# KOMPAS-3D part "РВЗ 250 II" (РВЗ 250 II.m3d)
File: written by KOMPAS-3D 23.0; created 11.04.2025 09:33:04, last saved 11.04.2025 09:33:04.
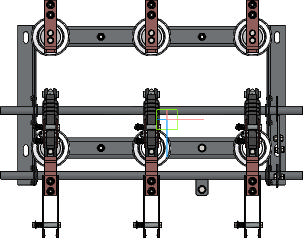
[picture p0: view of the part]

Document properties: Автор: pc; Полное имя файла: C:\Users\pc\Desktop\работа\РВЗ\3D макеты\РВЗ 250 II.m3d

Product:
- Body: Тело 1
    Масса: 0.01131
- Body: Тело 2
    Масса: 0.01131
- Body: Тело 3
    Масса: 0.01131
- Body: Тело 4
    Масса: 0.01131
- Body: Тело 5
    Масса: 1.849184
- Body: Тело 6
    Масса: 0.011176
- Body: Тело 7
    Масса: 0.011176
- Body: Тело 8
    Масса: 0.011176
- Body: Тело 9
    Масса: 0.052628
- Body: Тело 10
    Масса: 1.849184
- Body: Тело 11
    Масса: 0.010034
- Part/product: РВЗ 250 II
    Масса: 3.839795

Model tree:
1. Операция без истории:1
2. Операция без истории:2
3. Операция без истории:3
4. Операция без истории:4
5. Операция без истории:5
6. Операция без истории:6
7. Операция без истории:7
8. Операция без истории:8
9. Операция без истории:9
10. Операция без истории:10
11. Операция без истории:11
12. Поверхность без истории:1
13. Поверхность без истории:2
14. Поверхность без истории:3
15. Поверхность без истории:4
16. Поверхность без истории:5
17. Поверхность без истории:6
18. Поверхность без истории:7
19. Поверхность без истории:8
20. Поверхность без истории:9
21. Поверхность без истории:10
22. Поверхность без истории:11
23. Поверхность без истории:12
24. Поверхность без истории:13
25. Поверхность без истории:14
26. Поверхность без истории:15
27. Поверхность без истории:16
28. Поверхность без истории:17
29. Поверхность без истории:18
30. Поверхность без истории:19
31. Поверхность без истории:20
32. Поверхность без истории:21
33. Поверхность без истории:22
34. Поверхность без истории:23
35. Поверхность без истории:24
36. Поверхность без истории:25
37. Поверхность без истории:26
38. Поверхность без истории:27
39. Поверхность без истории:28
40. Поверхность без истории:29
41. Поверхность без истории:30
42. Поверхность без истории:31
43. Поверхность без истории:32
44. Поверхность без истории:33
45. Поверхность без истории:34
46. Поверхность без истории:35
47. Поверхность без истории:36
48. Поверхность без истории:37
49. Поверхность без истории:38
50. Поверхность без истории:39
51. Поверхность без истории:40
52. Поверхность без истории:41
53. Поверхность без истории:42
54. Поверхность без истории:43
55. Поверхность без истории:44
56. Поверхность без истории:45
57. Поверхность без истории:46
58. Поверхность без истории:47
59. Поверхность без истории:48
60. Поверхность без истории:49
61. Поверхность без истории:50
62. Поверхность без истории:51
63. Поверхность без истории:52
64. Поверхность без истории:53
65. Поверхность без истории:54
66. Поверхность без истории:55
67. Поверхность без истории:56
68. Поверхность без истории:57
69. Поверхность без истории:58
70. Поверхность без истории:59
71. Поверхность без истории:60
72. Поверхность без истории:61
73. Поверхность без истории:62
74. Поверхность без истории:63
75. Поверхность без истории:64
76. Поверхность без истории:65
77. Поверхность без истории:66
78. Поверхность без истории:67
79. Поверхность без истории:68
80. Поверхность без истории:69
81. Поверхность без истории:70
82. Поверхность без истории:71
83. Поверхность без истории:72
84. Поверхность без истории:73
85. Поверхность без истории:74
86. Поверхность без истории:75
87. Поверхность без истории:76
88. Поверхность без истории:77
89. Поверхность без истории:78
90. Поверхность без истории:79
91. Поверхность без истории:80
92. Поверхность без истории:81
93. Поверхность без истории:82
94. Поверхность без истории:83
95. Поверхность без истории:84
96. Поверхность без истории:85
97. Поверхность без истории:86
98. Поверхность без истории:87
99. Поверхность без истории:88
100. Поверхность без истории:89
101. Поверхность без истории:90
102. Поверхность без истории:91
103. Поверхность без истории:92
104. Поверхность без истории:93
105. Поверхность без истории:94
106. Поверхность без истории:95
107. Поверхность без истории:96
108. Поверхность без истории:97
109. Поверхность без истории:98
110. Поверхность без истории:99
111. Поверхность без истории:100
112. Поверхность без истории:101
113. Поверхность без истории:102
114. Поверхность без истории:103
115. Поверхность без истории:104
116. Поверхность без истории:105
117. Поверхность без истории:106
118. Поверхность без истории:107
119. Поверхность без истории:108
120. Поверхность без истории:109
121. Поверхность без истории:110
122. Поверхность без истории:111
123. Поверхность без истории:112
124. Поверхность без истории:113
125. Поверхность без истории:114
126. Поверхность без истории:115
127. Поверхность без истории:116
128. Поверхность без истории:117
129. Поверхность без истории:118
130. Поверхность без истории:119
131. Поверхность без истории:120
132. Поверхность без истории:121
133. Поверхность без истории:122
134. Поверхность без истории:123
135. Поверхность без истории:124
136. Поверхность без истории:125
137. Поверхность без истории:126
138. Поверхность без истории:127
139. Поверхность без истории:128
140. Поверхность без истории:129
141. Поверхность без истории:130
142. Поверхность без истории:131
143. Поверхность без истории:132
144. Поверхность без истории:133
145. Поверхность без истории:134
146. Поверхность без истории:135
147. Поверхность без истории:136
148. Поверхность без истории:137
149. Поверхность без истории:138
150. Поверхность без истории:139
151. Поверхность без истории:140
152. Поверхность без истории:141
153. Поверхность без истории:142
154. Поверхность без истории:143
155. Поверхность без истории:144
156. Поверхность без истории:145
157. Поверхность без истории:146
158. Поверхность без истории:147
159. Поверхность без истории:148
160. Поверхность без истории:149
161. Поверхность без истории:150
162. Поверхность без истории:151
163. Поверхность без истории:152
164. Поверхность без истории:153
165. Поверхность без истории:154
166. Поверхность без истории:155
167. Поверхность без истории:156
168. Поверхность без истории:157
169. Поверхность без истории:158
170. Поверхность без истории:159
171. Поверхность без истории:160
172. Поверхность без истории:161
173. Поверхность без истории:162
174. Поверхность без истории:163
175. Поверхность без истории:164
176. Поверхность без истории:165
177. Поверхность без истории:166
178. Поверхность без истории:167
179. Поверхность без истории:168
180. Поверхность без истории:169
181. Поверхность без истории:170
182. Поверхность без истории:171
183. Поверхность без истории:172
184. Поверхность без истории:173
185. Поверхность без истории:174
186. Поверхность без истории:175
187. Поверхность без истории:176
188. Поверхность без истории:177
189. Поверхность без истории:178
190. Поверхность без истории:179
191. Поверхность без истории:180
192. Поверхность без истории:181
193. Поверхность без истории:182
194. Поверхность без истории:183
195. Поверхность без истории:184
196. Поверхность без истории:185
197. Поверхность без истории:186
198. Поверхность без истории:187
199. Поверхность без истории:188
200. Поверхность без истории:189
201. Поверхность без истории:190
202. Поверхность без истории:191
203. Поверхность без истории:192
204. Поверхность без истории:193
205. Поверхность без истории:194
206. Поверхность без истории:195
207. Поверхность без истории:196
208. Поверхность без истории:197
209. Поверхность без истории:198
210. Поверхность без истории:199
211. Поверхность без истории:200
212. Поверхность без истории:201
213. Поверхность без истории:202
214. Поверхность без истории:203
215. Поверхность без истории:204
216. Поверхность без истории:205
217. Поверхность без истории:206
218. Поверхность без истории:207
219. Поверхность без истории:208
220. Поверхность без истории:209
221. Поверхность без истории:210
222. Поверхность без истории:211
223. Поверхность без истории:212
224. Поверхность без истории:213
225. Поверхность без истории:214
226. Поверхность без истории:215
227. Поверхность без истории:216
228. Поверхность без истории:217
229. Поверхность без истории:218
230. Поверхность без истории:219
231. Поверхность без истории:220
232. Поверхность без истории:221
233. Поверхность без истории:222
234. Поверхность без истории:223
235. Поверхность без истории:224
236. Поверхность без истории:225
237. Поверхность без истории:226
238. Поверхность без истории:227
239. Поверхность без истории:228
240. Поверхность без истории:229
241. Поверхность без истории:230
242. Поверхность без истории:231
243. Поверхность без истории:232
244. Поверхность без истории:233
245. Поверхность без истории:234
246. Поверхность без истории:235
247. Поверхность без истории:236
248. Поверхность без истории:237
249. Поверхность без истории:238
250. Поверхность без истории:239
251. Поверхность без истории:240
252. Поверхность без истории:241
253. Поверхность без истории:242
254. Поверхность без истории:243
255. Поверхность без истории:244
256. Поверхность без истории:245
257. Поверхность без истории:246
258. Поверхность без истории:247
259. Поверхность без истории:248
260. Поверхность без истории:249
261. Поверхность без истории:250
262. Поверхность без истории:251
263. Поверхность без истории:252
264. Поверхность без истории:253
265. Поверхность без истории:254
266. Поверхность без истории:255
267. Поверхность без истории:256
268. Поверхность без истории:257
269. Поверхность без истории:258
270. Поверхность без истории:259
271. Поверхность без истории:260
272. Поверхность без истории:261
273. Поверхность без истории:262
274. Поверхность без истории:263
275. Поверхность без истории:264
276. Поверхность без истории:265
277. Поверхность без истории:266
278. Поверхность без истории:267
279. Поверхность без истории:268
280. Поверхность без истории:269
281. Поверхность без истории:270
282. Поверхность без истории:271
283. Поверхность без истории:272
284. Поверхность без истории:273
285. Поверхность без истории:274
286. Поверхность без истории:275
287. Поверхность без истории:276
288. Поверхность без истории:277
289. Поверхность без истории:278
290. Поверхность без истории:279
291. Поверхность без истории:280
292. Поверхность без истории:281
293. Поверхность без истории:282
294. Поверхность без истории:283
295. Поверхность без истории:284
296. Поверхность без истории:285
297. Поверхность без истории:286
298. Поверхность без истории:287
299. Поверхность без истории:288
300. Поверхность без истории:289
301. Поверхность без истории:290
302. Поверхность без истории:291
303. Поверхность без истории:292
304. Поверхность без истории:293
305. Поверхность без истории:294
306. Поверхность без истории:295
307. Поверхность без истории:296
308. Поверхность без истории:297
309. Поверхность без истории:298
310. Поверхность без истории:299
311. Поверхность без истории:300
